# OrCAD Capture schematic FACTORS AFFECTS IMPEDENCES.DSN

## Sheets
1 PAGE2: size A4
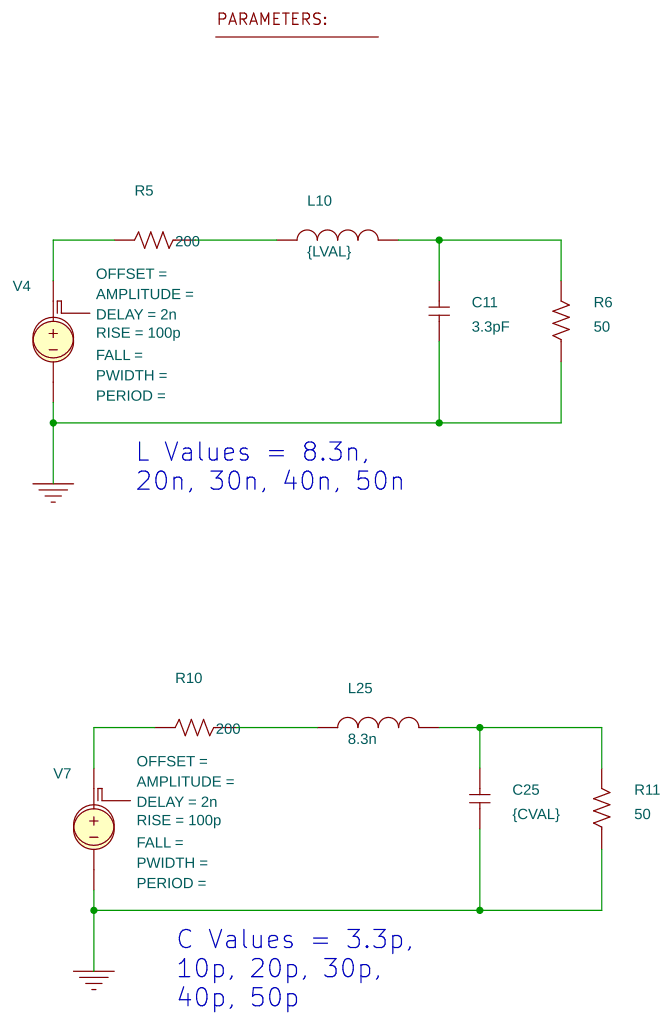
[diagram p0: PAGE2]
2 PAGE1: size A4
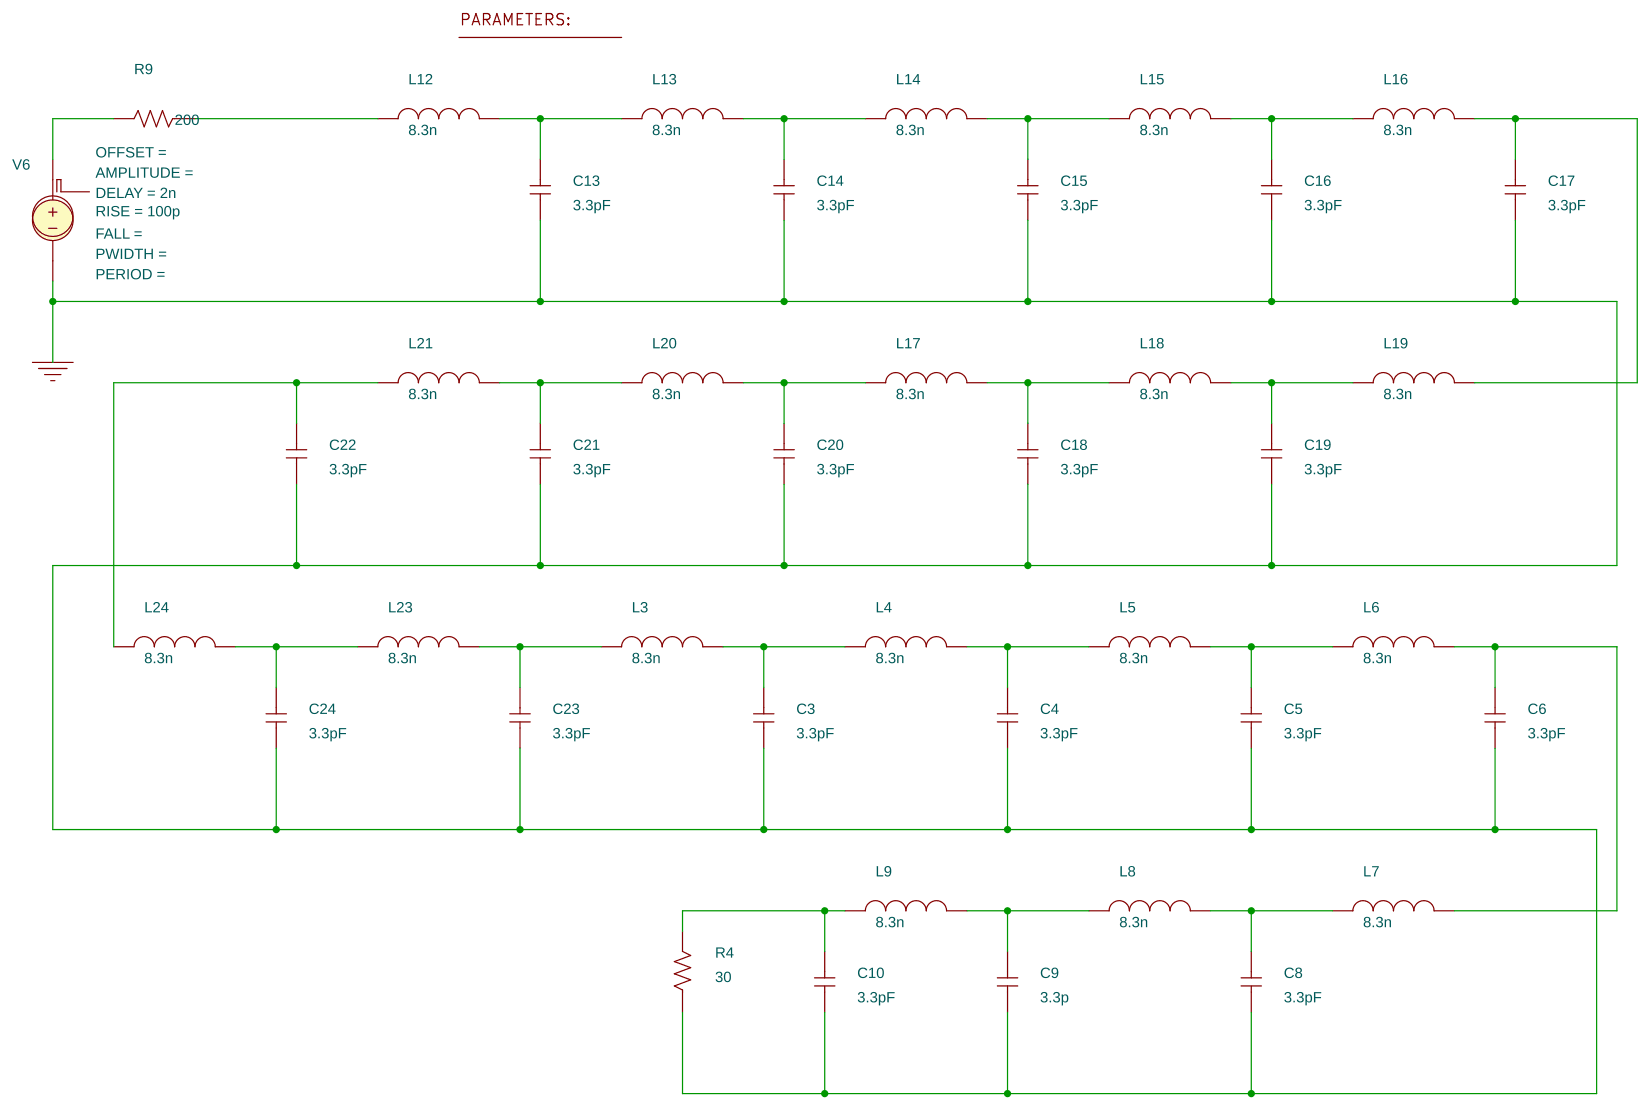
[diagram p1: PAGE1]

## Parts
sheet PAGE1
2  PARAM
C3  3.3pF  [CK05]
C4  3.3pF  [CK05]
C5  3.3pF  [CK05]
C6  3.3pF  [CK05]
C8  3.3pF  [CK05]
C9  3.3p  [CK05]
C10  3.3pF  [CK05]
C13  3.3pF  [CK05]
C14  3.3pF  [CK05]
C15  3.3pF  [CK05]
C16  3.3pF  [CK05]
C17  3.3pF  [CK05]
C18  3.3pF  [CK05]
C19  3.3pF  [CK05]
C20  3.3pF  [CK05]
C21  3.3pF  [CK05]
C22  3.3pF  [CK05]
C23  3.3pF  [CK05]
C24  3.3pF  [CK05]
L3  8.3n  [L2012C]
L4  8.3n  [L2012C]
L5  8.3n  [L2012C]
L6  8.3n  [L2012C]
L7  8.3n  [L2012C]
L8  8.3n  [L2012C]
L9  8.3n  [L2012C]
L12  8.3n  [L2012C]
L13  8.3n  [L2012C]
L14  8.3n  [L2012C]
L15  8.3n  [L2012C]
L16  8.3n  [L2012C]
L17  8.3n  [L2012C]
L18  8.3n  [L2012C]
L19  8.3n  [L2012C]
L20  8.3n  [L2012C]
L21  8.3n  [L2012C]
L23  8.3n  [L2012C]
L24  8.3n  [L2012C]
R4  30  [RC05]
R9  200  [RC05]
V6  ?DC|DC @DC| ?AC|AC @AC|\n+PULSE @OFFSET @AMPLITUDE+@OFFSET ?DELAY/@DELAY/~DELAY/0/ #RISE/@RISE/ #FALL/@FALL/ #PWIDTH/@PWIDTH/ #PERIOD/@PERIOD/
sheet PAGE2
3  PARAM
C11  3.3pF  [CK05]
C25  {CVAL}  [CK05]
L10  {LVAL}  [L2012C]
L25  8.3n  [L2012C]
R5  200  [RC05]
R6  50  [RC05]
R10  200  [RC05]
R11  50  [RC05]
V4  ?DC|DC @DC| ?AC|AC @AC|\n+PULSE @OFFSET @AMPLITUDE+@OFFSET ?DELAY/@DELAY/~DELAY/0/ #RISE/@RISE/ #FALL/@FALL/ #PWIDTH/@PWIDTH/ #PERIOD/@PERIOD/
V7  ?DC|DC @DC| ?AC|AC @AC|\n+PULSE @OFFSET @AMPLITUDE+@OFFSET ?DELAY/@DELAY/~DELAY/0/ #RISE/@RISE/ #FALL/@FALL/ #PWIDTH/@PWIDTH/ #PERIOD/@PERIOD/

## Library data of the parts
2 = PARAM: CVAL: 3.8pF
C3-C6 C8-C11 C13-C25 = C
L3-L10 L12-L21 L23-L25 = L
R4-R6 R9-R11 = R
V4 V6 V7 = V_PULSE: DELAY: 2n; RISE: 100p
3 = PARAM: CVAL: 3.3p; LVAL: 8.3n

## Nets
0: C3.1 C4.1 C5.1 C6.1 C8.1 C9.1 C10.1 C11.1 C13.1 C14.1 C15.1 C16.1 C17.1 C18.1 C19.1 C20.1 C21.1 C22.1 C23.1 C24.1 C25.1 R4.1 R6.1 R11.1 V4.1(NVS) V6.1(NVS) V7.1(NVS)
N12682: C3.2 L3.2 L4.1
N13432: C4.2 L4.2 L5.1
N13570: C5.2 L5.2 L6.1
N13710: C6.2 L6.2 L7.2
N13852: C8.2 L7.1 L8.2
N13978: C9.2 L8.1 L9.2
N14984: R5.2 V4.2(PVS)
N14994: L10.1 R5.1
N15000: C11.2 L10.2 R6.2
N16387: C10.2 L9.1 R4.2
N17154: R9.2 V6.2(PVS)
N17164: L12.1 R9.1
N17170: C13.2 L12.2 L13.1
N17184: C14.2 L13.2 L14.1
N17200: C15.2 L14.2 L15.1
N17216: C16.2 L15.2 L16.1
N17232: C17.2 L16.2 L19.2
N17502: C18.2 L17.2 L18.1
N17518: C19.2 L18.2 L19.1
N17811: C20.2 L17.1 L20.2
N18002: C21.2 L20.1 L21.2
N18252: C22.2 L21.1 L24.1
N18517: C23.2 L3.1 L23.2
N18665: C24.2 L23.1 L24.2
N20222: R10.2 V7.2(PVS)
N20232: L25.1 R10.1
N20238: C25.2 L25.2 R11.2

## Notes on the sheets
sheet 1
- L Values = 8.3n,
  20n, 30n, 40n, 50n
- C Values = 3.3p,
  10p, 20p, 30p,
  40p, 50p
